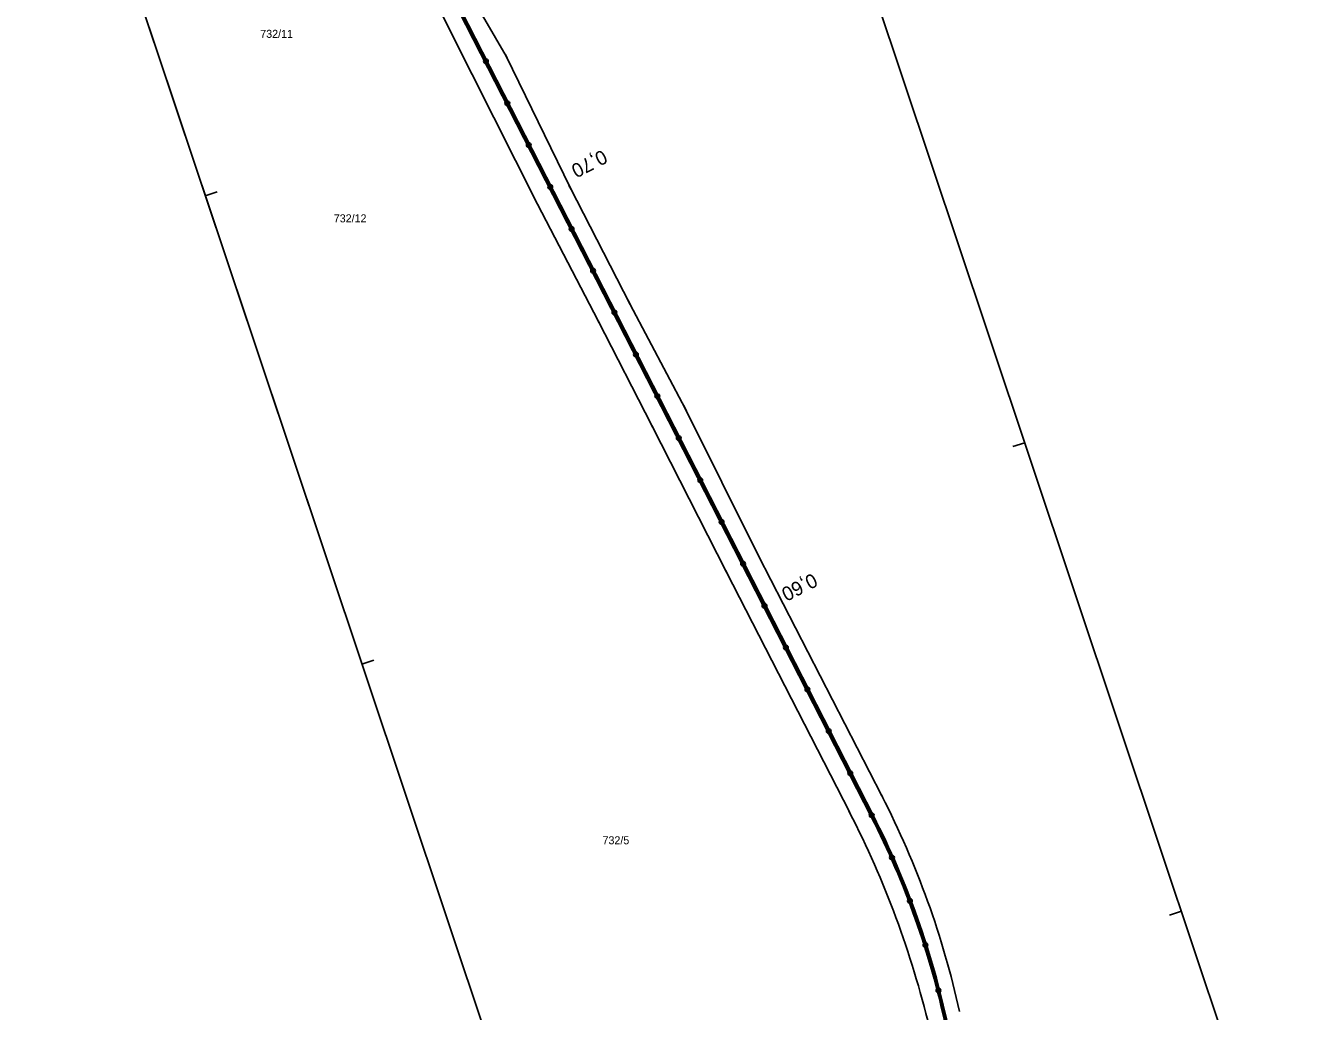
# Model space of a CAD drawing. Extents: x -548552 to -543113, y -1131925 to -1123599.
# Drawn here: x -547535.9 to -547263.3, y -1126224.7 to -1126015.1 of the extents above; entities that cross this region are included whole.
import ezdxf

# ---------------------------------------------------------------- set-up
doc = ezdxf.new("R2010")
doc.units = 0
for name, color, linetype in [('Parcelní čísla', 7, 'Continuous'), ('Profile', 7, 'Continuous'), ('PROFILY NÁVRH', 7, 'Continuous'), ('STANIČENÍ', 7, 'Continuous')]:
    doc.layers.add(name, color=color, linetype=linetype)

msp = doc.modelspace()

# ---------------------------------------------------------------- linework, layer by layer
at = {"layer": 'Profile'}
for p, q in [((-547535.88, -1125937.11), (-547472.4, -1126127.03)), ((-547368.83, -1125968.44), (-547331.56, -1126079.95)), ((-547509.67, -1126015.52), (-547472.4, -1126127.03)), ((-547495.21, -1126050.47), (-547497.71, -1126051.3)), ((-547331.56, -1126079.95), (-547294.28, -1126191.46)), ((-547323.58, -1126103.81), (-547326.09, -1126104.64)), ((-547472.4, -1126127.03), (-547435.12, -1126238.54)), ((-547472.4, -1126127.03), (-547435.12, -1126238.54)), ((-547461.92, -1126150.05), (-547464.42, -1126150.89)), ((-547294.28, -1126191.46), (-547263.31, -1126284.1)), ((-547290.29, -1126203.39), (-547292.8, -1126204.23))]:
    msp.add_line(p, q, dxfattribs=at)
at = {"layer": 'PROFILY NÁVRH'}
for p, q in [((-547356.19, -1126183.35), (-547499.63, -1125902.98)), ((-547355.74, -1126183.12), (-547499.18, -1125902.75)), ((-547449.32, -1125994.74), (-547433.76, -1126021.6)), ((-547454.91, -1125997.6), (-547441.1, -1126025.35)), ((-547433.76, -1126021.6), (-547420.2, -1126049.53)), ((-547441.1, -1126025.35), (-547427.11, -1126053.07)), ((-547420.2, -1126049.53), (-547407.4, -1126074.4)), ((-547427.11, -1126053.07), (-547414.25, -1126077.91)), ((-547407.4, -1126074.4), (-547395.73, -1126096.5)), ((-547414.25, -1126077.91), (-547402.85, -1126100.14)), ((-547395.73, -1126096.5), (-547380.13, -1126127.83)), ((-547402.85, -1126100.14), (-547386.94, -1126131.32)), ((-547380.13, -1126127.83), (-547353.94, -1126178.9)), ((-547386.94, -1126131.32), (-547360.78, -1126182.41))]:
    msp.add_line(p, q, dxfattribs=at)
for centre, radius, start, end in [((-547522.97, -1126265.61), 189.98, 12.4338, 27.154), ((-547544.91, -1126276.69), 206.86, 13.585, 27.1141)]:
    msp.add_arc(centre, radius, start, end, dxfattribs=at)
for major_axis in [(-85.22, 158.26), (-85.46, 158.7)]:
    msp.add_ellipse((-547516.21, -1126265.22), major_axis=major_axis, ratio=0.999998, start_param=4.428044, end_param=4.691325, dxfattribs=at)
at = {"layer": 'STANIČENÍ'}
for p, q in [((-547355.97, -1126183.23), (-547499.4, -1125902.86)), ((-547433.54, -1126022.03), (-547433.92, -1126021.28)), ((-547441.01, -1126025.53), (-547441.13, -1126025.28)), ((-547419.96, -1126050), (-547420.43, -1126049.09)), ((-547407.14, -1126074.9), (-547407.91, -1126073.4)), ((-547414.09, -1126078.22), (-547414.39, -1126077.65)), ((-547395.44, -1126097.07), (-547396.04, -1126095.91)), ((-547402.63, -1126100.57), (-547403.02, -1126099.8)), ((-547379.57, -1126128.94), (-547380.55, -1126127)), ((-547386.67, -1126131.84), (-547387.15, -1126130.91)), ((-547353.76, -1126179.25), (-547354.1, -1126178.58)), ((-547360.61, -1126182.75), (-547360.94, -1126182.11))]:
    msp.add_line(p, q, dxfattribs=at)
for centre, radius in [((-547441.74, -1126015.57), 0.1), ((-547441.29, -1126016.46), 0.1), ((-547440.83, -1126017.35), 0.1), ((-547440.37, -1126018.24), 0.1), ((-547439.92, -1126019.13), 0.1), ((-547439.46, -1126020.02), 0.1), ((-547439.01, -1126020.91), 0.1), ((-547438.55, -1126021.8), 0.1), ((-547438.09, -1126022.71), 0.5), ((-547438.1, -1126022.7), 0.1), ((-547437.64, -1126023.59), 0.1), ((-547437.19, -1126024.48), 0.1), ((-547436.73, -1126025.37), 0.1), ((-547436.28, -1126026.26), 0.1), ((-547435.82, -1126027.15), 0.1), ((-547435.36, -1126028.04), 0.1), ((-547434.91, -1126028.93), 0.1), ((-547434.45, -1126029.82), 0.1), ((-547434, -1126030.71), 0.1), ((-547433.53, -1126031.62), 0.5), ((-547433.54, -1126031.6), 0.1), ((-547433.09, -1126032.49), 0.1), ((-547432.63, -1126033.38), 0.1), ((-547432.18, -1126034.27), 0.1), ((-547431.72, -1126035.16), 0.1), ((-547431.27, -1126036.05), 0.1), ((-547431.26, -1126036.07), 0.1), ((-547430.81, -1126036.94), 0.1), ((-547430.8, -1126036.96), 0.1), ((-547430.35, -1126037.83), 0.1), ((-547429.9, -1126038.72), 0.1), ((-547429.44, -1126039.61), 0.1), ((-547428.98, -1126040.52), 0.5), ((-547428.99, -1126040.5), 0.1), ((-547428.53, -1126041.39), 0.1), ((-547428.08, -1126042.28), 0.1), ((-547427.62, -1126043.17), 0.1), ((-547427.17, -1126044.06), 0.1), ((-547426.71, -1126044.95), 0.1), ((-547426.26, -1126045.84), 0.1), ((-547425.8, -1126046.73), 0.1), ((-547425.34, -1126047.62), 0.1), ((-547424.89, -1126048.51), 0.1), ((-547424.42, -1126049.42), 0.5), ((-547424.43, -1126049.4), 0.1), ((-547423.98, -1126050.29), 0.1), ((-547423.52, -1126051.18), 0.1), ((-547423.07, -1126052.08), 0.1), ((-547422.61, -1126052.97), 0.1), ((-547422.16, -1126053.86), 0.1), ((-547421.7, -1126054.75), 0.1), ((-547421.24, -1126055.64), 0.1), ((-547420.79, -1126056.53), 0.1), ((-547420.33, -1126057.42), 0.1), ((-547419.87, -1126058.33), 0.5), ((-547419.88, -1126058.31), 0.1), ((-547419.42, -1126059.2), 0.1), ((-547418.97, -1126060.09), 0.1), ((-547418.51, -1126060.98), 0.1), ((-547418.06, -1126061.87), 0.1), ((-547417.6, -1126062.76), 0.1), ((-547417.15, -1126063.65), 0.1), ((-547416.69, -1126064.54), 0.1), ((-547416.23, -1126065.43), 0.1), ((-547415.78, -1126066.32), 0.1), ((-547415.31, -1126067.23), 0.5), ((-547415.32, -1126067.21), 0.1), ((-547414.87, -1126068.1), 0.1), ((-547414.41, -1126068.99), 0.1), ((-547413.96, -1126069.88), 0.1), ((-547413.5, -1126070.77), 0.1), ((-547413.05, -1126071.66), 0.1), ((-547412.59, -1126072.55), 0.1), ((-547412.14, -1126073.44), 0.1), ((-547411.68, -1126074.33), 0.1), ((-547411.22, -1126075.22), 0.1), ((-547410.76, -1126076.13), 0.5), ((-547410.77, -1126076.11), 0.1), ((-547410.31, -1126077), 0.1), ((-547409.86, -1126077.89), 0.1), ((-547409.4, -1126078.78), 0.1), ((-547408.95, -1126079.67), 0.1), ((-547408.49, -1126080.57), 0.1), ((-547408.04, -1126081.46), 0.1), ((-547407.58, -1126082.35), 0.1), ((-547407.13, -1126083.24), 0.1), ((-547406.67, -1126084.13), 0.1), ((-547406.21, -1126085.03), 0.5), ((-547406.21, -1126085.02), 0.1), ((-547405.76, -1126085.91), 0.1), ((-547405.3, -1126086.8), 0.1), ((-547404.85, -1126087.69), 0.1), ((-547404.39, -1126088.58), 0.1), ((-547403.94, -1126089.47), 0.1), ((-547403.48, -1126090.36), 0.1), ((-547403.03, -1126091.25), 0.1), ((-547402.57, -1126092.14), 0.1), ((-547402.11, -1126093.03), 0.1), ((-547401.65, -1126093.94), 0.5), ((-547401.66, -1126093.92), 0.1), ((-547401.2, -1126094.81), 0.1), ((-547400.75, -1126095.7), 0.1), ((-547400.29, -1126096.59), 0.1), ((-547399.84, -1126097.48), 0.1), ((-547399.38, -1126098.37), 0.1), ((-547398.93, -1126099.26), 0.1), ((-547398.47, -1126100.15), 0.1), ((-547398.02, -1126101.04), 0.1), ((-547397.56, -1126101.93), 0.1), ((-547397.1, -1126102.84), 0.5), ((-547397.1, -1126102.82), 0.1), ((-547396.65, -1126103.71), 0.1), ((-547396.19, -1126104.6), 0.1), ((-547395.74, -1126105.49), 0.1), ((-547395.28, -1126106.38), 0.1), ((-547394.83, -1126107.27), 0.1), ((-547394.37, -1126108.16), 0.1), ((-547393.92, -1126109.05), 0.1), ((-547393.46, -1126109.95), 0.1), ((-547393.01, -1126110.84), 0.1), ((-547392.54, -1126111.74), 0.5), ((-547392.55, -1126111.73), 0.1), ((-547392.09, -1126112.62), 0.1), ((-547391.64, -1126113.51), 0.1), ((-547391.18, -1126114.4), 0.1), ((-547390.73, -1126115.29), 0.1), ((-547390.27, -1126116.18), 0.1), ((-547389.82, -1126117.07), 0.1), ((-547389.36, -1126117.96), 0.1), ((-547388.91, -1126118.85), 0.1), ((-547388.45, -1126119.74), 0.1), ((-547387.99, -1126120.64), 0.5), ((-547388, -1126120.63), 0.1), ((-547387.54, -1126121.52), 0.1), ((-547387.08, -1126122.41), 0.1), ((-547386.63, -1126123.3), 0.1), ((-547386.17, -1126124.19), 0.1), ((-547385.72, -1126125.08), 0.1), ((-547385.26, -1126125.97), 0.1), ((-547384.81, -1126126.86), 0.1), ((-547384.35, -1126127.75), 0.1), ((-547383.9, -1126128.64), 0.1), ((-547383.43, -1126129.55), 0.5), ((-547383.44, -1126129.53), 0.1), ((-547382.98, -1126130.42), 0.1), ((-547382.53, -1126131.31), 0.1), ((-547382.07, -1126132.2), 0.1), ((-547381.62, -1126133.09), 0.1), ((-547381.16, -1126133.98), 0.1), ((-547380.71, -1126134.87), 0.1), ((-547380.25, -1126135.76), 0.1), ((-547379.8, -1126136.65), 0.1), ((-547379.34, -1126137.54), 0.1), ((-547378.88, -1126138.45), 0.5), ((-547378.89, -1126138.43), 0.1), ((-547378.43, -1126139.33), 0.1), ((-547377.97, -1126140.22), 0.1), ((-547377.52, -1126141.11), 0.1), ((-547377.06, -1126142), 0.1), ((-547376.61, -1126142.89), 0.1), ((-547376.15, -1126143.78), 0.1), ((-547375.7, -1126144.67), 0.1), ((-547375.24, -1126145.56), 0.1), ((-547374.79, -1126146.45), 0.1), ((-547374.32, -1126147.35), 0.5), ((-547374.33, -1126147.34), 0.1), ((-547373.88, -1126148.23), 0.1), ((-547373.42, -1126149.12), 0.1), ((-547372.96, -1126150.01), 0.1), ((-547372.51, -1126150.9), 0.1), ((-547372.05, -1126151.79), 0.1), ((-547371.6, -1126152.68), 0.1), ((-547371.14, -1126153.57), 0.1), ((-547370.69, -1126154.46), 0.1), ((-547370.23, -1126155.35), 0.1), ((-547369.77, -1126156.25), 0.5), ((-547369.78, -1126156.24), 0.1), ((-547369.32, -1126157.13), 0.1), ((-547368.87, -1126158.02), 0.1), ((-547368.41, -1126158.91), 0.1), ((-547367.95, -1126159.8), 0.1), ((-547367.5, -1126160.69), 0.1), ((-547367.04, -1126161.58), 0.1), ((-547366.59, -1126162.47), 0.1), ((-547366.13, -1126163.36), 0.1), ((-547365.68, -1126164.25), 0.1), ((-547365.21, -1126165.16), 0.5), ((-547365.22, -1126165.14), 0.1), ((-547364.77, -1126166.03), 0.1), ((-547364.31, -1126166.92), 0.1), ((-547363.85, -1126167.81), 0.1), ((-547363.4, -1126168.71), 0.1), ((-547362.94, -1126169.6), 0.1), ((-547362.49, -1126170.49), 0.1), ((-547362.03, -1126171.38), 0.1), ((-547361.58, -1126172.27), 0.1), ((-547361.12, -1126173.16), 0.1), ((-547360.66, -1126174.06), 0.5), ((-547360.67, -1126174.05), 0.1), ((-547360.21, -1126174.94), 0.1), ((-547359.76, -1126175.83), 0.1), ((-547359.3, -1126176.72), 0.1), ((-547358.84, -1126177.61), 0.1), ((-547358.39, -1126178.5), 0.1), ((-547357.93, -1126179.39), 0.1), ((-547357.48, -1126180.28), 0.1), ((-547357.02, -1126181.17), 0.1), ((-547356.57, -1126182.06), 0.1), ((-547356.11, -1126182.96), 0.5), ((-547356.11, -1126182.95), 0.1), ((-547355.66, -1126183.84), 0.1), ((-547355.21, -1126184.73), 0.1), ((-547354.76, -1126185.63), 0.1), ((-547354.32, -1126186.53), 0.1), ((-547353.89, -1126187.43), 0.1), ((-547353.46, -1126188.33), 0.1), ((-547353.03, -1126189.24), 0.1), ((-547352.61, -1126190.15), 0.1), ((-547352.2, -1126191.06), 0.1), ((-547351.79, -1126191.98), 0.5), ((-547351.79, -1126191.97), 0.1), ((-547351.39, -1126192.88), 0.1), ((-547350.99, -1126193.8), 0.1), ((-547350.59, -1126194.72), 0.1), ((-547350.2, -1126195.64), 0.1), ((-547349.82, -1126196.56), 0.1), ((-547349.44, -1126197.49), 0.1), ((-547349.07, -1126198.42), 0.1), ((-547348.7, -1126199.35), 0.1), ((-547347.97, -1126201.22), 0.5), ((-547348.34, -1126200.28), 0.1), ((-547347.98, -1126201.21), 0.1), ((-547347.62, -1126202.15), 0.1), ((-547347.28, -1126203.08), 0.1), ((-547346.93, -1126204.02), 0.1), ((-547346.6, -1126204.97), 0.1), ((-547346.26, -1126205.91), 0.1), ((-547345.94, -1126206.85), 0.1), ((-547345.62, -1126207.8), 0.1), ((-547345.3, -1126208.75), 0.1), ((-547344.68, -1126210.66), 0.5), ((-547344.99, -1126209.7), 0.1), ((-547344.68, -1126210.65), 0.1), ((-547344.38, -1126211.61), 0.1), ((-547344.09, -1126212.56), 0.1), ((-547343.8, -1126213.52), 0.1), ((-547343.51, -1126214.48), 0.1), ((-547343.23, -1126215.44), 0.1), ((-547342.96, -1126216.4), 0.1), ((-547342.69, -1126217.36), 0.1), ((-547342.43, -1126218.33), 0.1), ((-547341.91, -1126220.27), 0.5), ((-547342.17, -1126219.29), 0.1), ((-547341.92, -1126220.26), 0.1), ((-547341.67, -1126221.23), 0.1), ((-547341.43, -1126222.2), 0.1), ((-547341.19, -1126223.17), 0.1), ((-547340.96, -1126224.15), 0.1)]:
    msp.add_circle(centre, radius, dxfattribs=at)
msp.add_ellipse((-547516.21, -1126265.22), major_axis=(-85.34, 158.48), ratio=0.999998, start_param=4.428044, end_param=4.691325, dxfattribs=at)

# ---------------------------------------------------------------- texts
at = {"layer": 'Parcelní čísla'}
for s, p in [('732/11', (-547486.03, -1126017.72)), ('732/12', (-547470.41, -1126056.95)), ('732/5', (-547413.3, -1126189.18))]:
    msp.add_text(s, height=1.7, dxfattribs=at).set_placement(p)
at = {"layer": 'STANIČENÍ'}
for s, p in [('0,70', (-547413.29, -1126041.4)), ('0,60', (-547368.63, -1126131.42))]:
    msp.add_text(s, height=3, rotation=207.0941, dxfattribs=at).set_placement(p)

doc.saveas('drawing.dxf')
